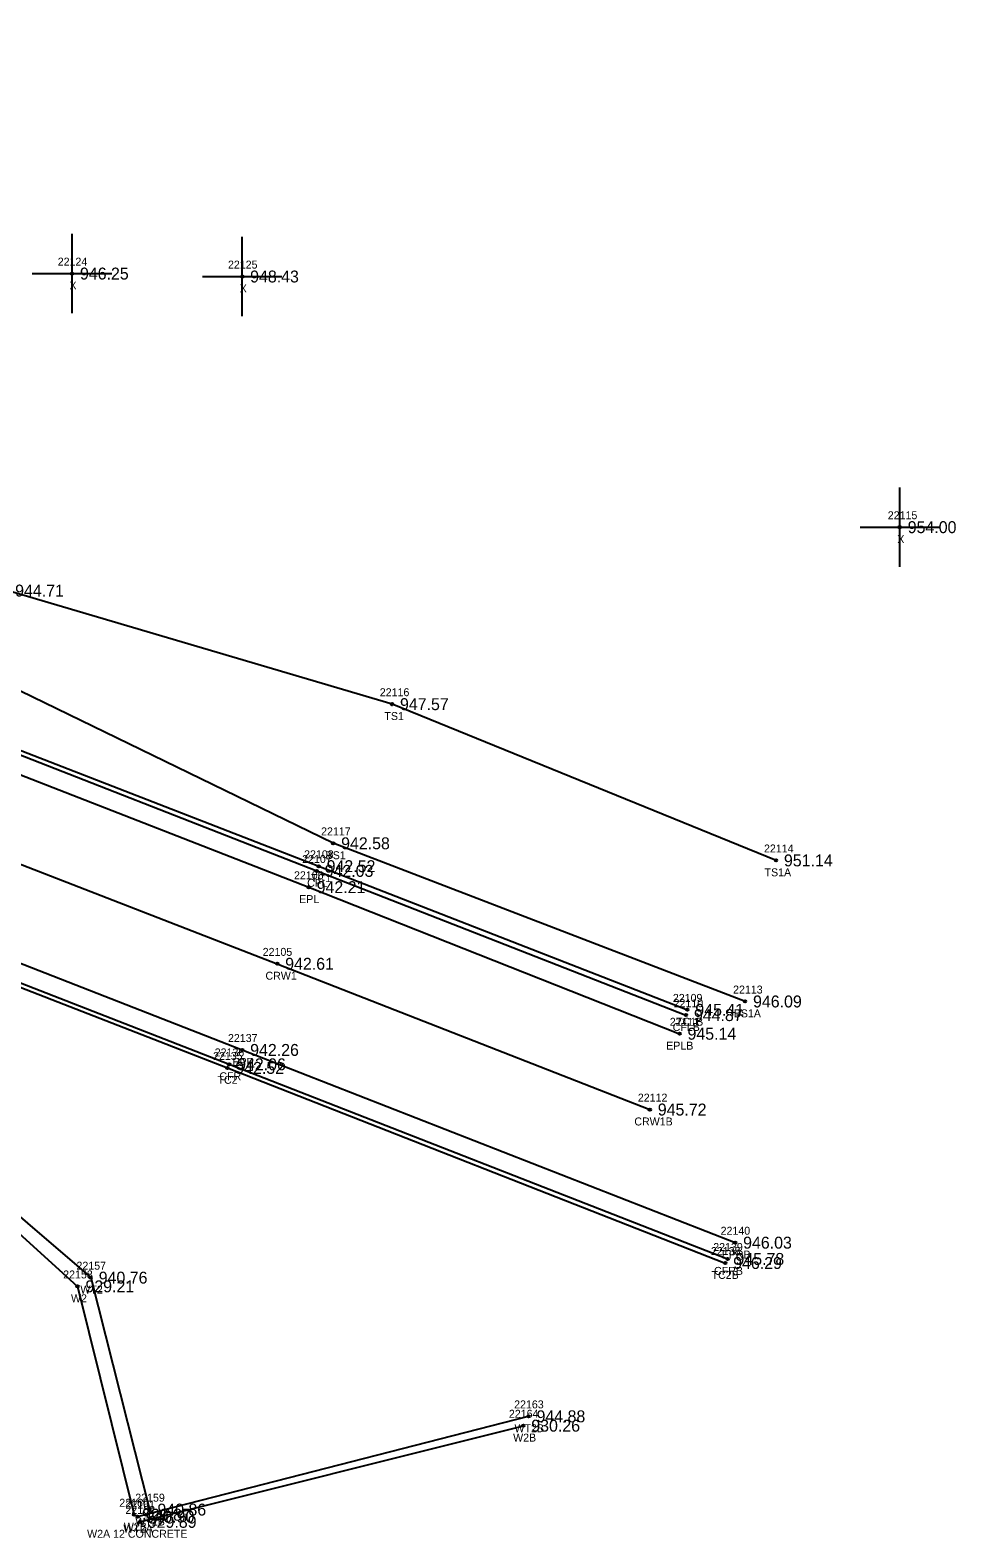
# Model space of a CAD drawing. Extents: x 1576181 to 1577685, y 1099396 to 1101490.
# Drawn here: x 1577568.7 to 1577685.3, y 1100751.9 to 1100941.6 of the extents above; entities that cross this region are included whole.
import ezdxf

# ---------------------------------------------------------------- set-up
doc = ezdxf.new("R2010")
doc.units = 0
for name, color, linetype in [('RD_DTM_BkLn1', 7, 'Continuous'), ('RD_DTM_BkLn2', 7, 'Continuous'), ('RD_DTM_BkLn_txCode', 7, 'Continuous'), ('RD_EX_BldgApp', 7, 'Continuous'), ('RD_EX_Conc', 7, 'Continuous'), ('RD_EX_Conc_txCode', 7, 'Continuous'), ('RD_EX_Misc', 7, 'Continuous'), ('RD_EX_Misc_txCode', 7, 'Continuous'), ('RD_EX_Road', 7, 'Continuous'), ('RD_EX_Road_txCode', 7, 'Continuous'), ('RD_EX_TX_Conc_ELEV', 7, 'Continuous'), ('RD_EX_TX_Misc_ELEV', 7, 'Continuous'), ('RD_EX_TX_Road_ELEV', 7, 'Continuous'), ('RD_HC_Survey_ELEV', 7, 'Continuous'), ('RD_HC_Survey_txCode', 7, 'Continuous'), ('RD_SMD_Locator', 7, 'Continuous')]:
    doc.layers.add(name, color=color, linetype=linetype)

msp = doc.modelspace()

# ---------------------------------------------------------------- linework, layer by layer
at = {"layer": 'RD_DTM_BkLn1'}
msp.add_lwpolyline([(1577238.59, 1101054.64), (1577263.64, 1101036.24), (1577303.95, 1101006.72), (1577344.58, 1100977.95), (1577386.9, 1100948.15), (1577426.17, 1100919.26), (1577465.69, 1100889.09), (1577507.94, 1100862.82), (1577553.41, 1100842.12), (1577599.84, 1100824.14), (1577646.74, 1100805.8)], dxfattribs=at)
at = {"layer": 'RD_DTM_BkLn2'}
msp.add_line((1577582.27, 1100754.58), (1577631.48, 1100767.2), dxfattribs=at)
for points in [[(1577662.62, 1100837.15), (1577614.29, 1100856.81), (1577565.85, 1100871.1), (1577528.46, 1100887.57), (1577543.38, 1100922.33)], [(1577395.54, 1100920.23), (1577401.33, 1100918.75), (1577405.58, 1100916.45), (1577417.84, 1100907.66), (1577459.24, 1100877.93), (1577501.01, 1100850.46), (1577548.36, 1100828.61), (1577593.56, 1100811.04), (1577656.23, 1100786.49)], [(1577522.49, 1100891.97), (1577519.6, 1100884.45), (1577518.53, 1100878.68), (1577519.8, 1100874.02), (1577525.54, 1100868.86), (1577559.77, 1100854.01), (1577605.06, 1100836.42), (1577651.47, 1100818.35)], [(1577658.73, 1100819.4), (1577606.88, 1100839.3), (1577561.44, 1100861.37), (1577525.46, 1100877.1), (1577521.55, 1100887.46)], [(1577432.53, 1100853.96), (1577434.36, 1100852.19), (1577447.88, 1100856.09), (1577457.13, 1100856.82), (1577470.14, 1100851.87), (1577480.17, 1100839.59), (1577486.13, 1100817.13), (1577494.64, 1100804.62), (1577509.91, 1100799.91), (1577531.35, 1100805.03), (1577541.32, 1100806.67), (1577560.38, 1100798.33), (1577576.37, 1100784.65), (1577583.76, 1100755.46)]]:
    msp.add_lwpolyline(points, dxfattribs=at)
at = {"layer": 'RD_EX_BldgApp'}
msp.add_line((1577582.55, 1100753.92), (1577630.82, 1100766.02), dxfattribs=at)
msp.add_lwpolyline([(1577431.47, 1100853.57), (1577434.21, 1100851.02), (1577448.25, 1100855.22), (1577457, 1100855.58), (1577470.32, 1100850.24), (1577479.05, 1100838.66), (1577484.72, 1100816.57), (1577493.67, 1100803.21), (1577510, 1100798.11), (1577531.96, 1100803.27), (1577542, 1100804.92), (1577559.8, 1100797.02), (1577574.7, 1100783.55), (1577581.82, 1100754.82)], dxfattribs=at)
at = {"layer": 'RD_EX_Conc'}
for points in [[(1577395.74, 1100920.66), (1577401.57, 1100919.25), (1577405.99, 1100917), (1577418.29, 1100908.16), (1577459.56, 1100878.43), (1577501.42, 1100850.96), (1577548.66, 1100829.07), (1577593.79, 1100811.49), (1577656.52, 1100787)], [(1577521.96, 1100892.21), (1577519.03, 1100884.74), (1577517.86, 1100878.7), (1577519.28, 1100873.69), (1577525.34, 1100868.31), (1577559.49, 1100853.53), (1577604.81, 1100835.83), (1577651.29, 1100817.68)]]:
    msp.add_lwpolyline(points, dxfattribs=at)
at = {"layer": 'RD_EX_Misc'}
for p, q in [((1577574.01, 1100905.99), (1577574.01, 1100915.99)), ((1577595.43, 1100905.62), (1577595.43, 1100915.62)), ((1577569.01, 1100910.99), (1577579.01, 1100910.99)), ((1577590.43, 1100910.62), (1577600.43, 1100910.62)), ((1577678.2, 1100874.08), (1577678.2, 1100884.08)), ((1577673.2, 1100879.08), (1577683.2, 1100879.08))]:
    msp.add_line(p, q, dxfattribs=at)
at = {"layer": 'RD_EX_Road'}
for points in [[(1577532.83, 1100925.69), (1577520.07, 1100893.35), (1577517.12, 1100885.44), (1577515.83, 1100878.7), (1577517.19, 1100872.6), (1577524.62, 1100866.38), (1577558.24, 1100851.54), (1577603.8, 1100833.78), (1577650.48, 1100815.34)], [(1577419.5, 1100910.06), (1577460.72, 1100880.37), (1577502.61, 1100852.88), (1577549.63, 1100831.2), (1577595.43, 1100813.3), (1577657.48, 1100789.05)]]:
    msp.add_lwpolyline(points, dxfattribs=at)
at = {"layer": 'RD_SMD_Locator'}
for centre in [(1577574.01, 1100910.99), (1577595.43, 1100910.62), (1577678.2, 1100879.08), (1577614.29, 1100856.81), (1577606.88, 1100839.3), (1577605.06, 1100836.42), (1577662.62, 1100837.15), (1577604.81, 1100835.83), (1577603.8, 1100833.78), (1577599.84, 1100824.14), (1577658.73, 1100819.4), (1577651.29, 1100817.68), (1577651.47, 1100818.35), (1577650.48, 1100815.34), (1577595.43, 1100813.3), (1577593.79, 1100811.49), (1577593.56, 1100811.04), (1577646.74, 1100805.8), (1577657.48, 1100789.05), (1577656.52, 1100787), (1577656.23, 1100786.49), (1577574.7, 1100783.55), (1577576.37, 1100784.65), (1577630.82, 1100766.02), (1577631.48, 1100767.2), (1577581.82, 1100754.82), (1577582.27, 1100754.58), (1577583.76, 1100755.46), (1577582.55, 1100753.92)]:
    msp.add_circle(centre, 0.15, dxfattribs=at)

# ---------------------------------------------------------------- texts
at = {"layer": 'RD_DTM_BkLn_txCode'}
for s, p in [('22116', (1577612.75, 1100857.81)), ('TS1', (1577613.33, 1100854.81)), ('22117', (1577605.36, 1100840.3)), ('BS1', (1577605.93, 1100837.3)), ('22114', (1577661.11, 1100838.15)), ('TS1A', (1577661.18, 1100835.15)), ('22113', (1577657.22, 1100820.4)), ('BS1A', (1577657.3, 1100817.4))]:
    msp.add_text(s, height=1, dxfattribs=at).set_placement(p)
at = {"layer": 'RD_EX_Conc_txCode'}
for s, p in [('22108', (1577603.22, 1100837.42)), ('22107', (1577602.98, 1100836.83)), ('CFL', (1577603.61, 1100833.83)), ('TC1', (1577604.09, 1100834.42)), ('22109', (1577649.64, 1100819.35)), ('22110', (1577649.74, 1100818.68)), ('TC1B', (1577650.04, 1100816.35)), ('CFLB', (1577649.61, 1100815.68)), ('22136', (1577591.97, 1100812.49)), ('22135', (1577591.76, 1100812.04)), ('TC2', (1577592.32, 1100809.04)), ('CFR', (1577592.56, 1100809.49)), ('22139', (1577654.72, 1100788)), ('22138', (1577654.43, 1100787.49)), ('TC2B', (1577654.51, 1100784.49)), ('CFRB', (1577654.82, 1100785))]:
    msp.add_text(s, height=1, dxfattribs=at).set_placement(p)
at = {"layer": 'RD_EX_Misc_txCode'}
for s, p in [('22124', (1577572.21, 1100911.99)), ('22125', (1577593.64, 1100911.62)), ('X', (1577573.69, 1100908.99)), ('X', (1577595.12, 1100908.62)), ('22115', (1577676.69, 1100880.08)), ('X', (1577677.89, 1100877.08)), ('22158', (1577572.9, 1100784.55)), ('22157', (1577574.57, 1100785.65)), ('WT2', (1577575.06, 1100782.65)), ('W2', (1577573.88, 1100781.55)), ('22164', (1577629, 1100767.02)), ('22163', (1577629.66, 1100768.2)), ('WT2B', (1577629.7, 1100765.2)), ('W2B', (1577629.53, 1100764.02)), ('22160', (1577579.96, 1100755.82)), ('22161', (1577580.73, 1100755.58)), ('22159', (1577581.97, 1100756.46)), ('22162', (1577580.73, 1100754.92)), ('W2A 12 CONCRETE', (1577575.91, 1100751.92)), ('WT2A', (1577580.47, 1100752.58)), ('W2B', (1577580.53, 1100752.82)), ('WT2B', (1577581.98, 1100753.46))]:
    msp.add_text(s, height=1, dxfattribs=at).set_placement(p)
at = {"layer": 'RD_EX_Road_txCode'}
for s, p in [('22106', (1577601.95, 1100834.78)), ('EPL', (1577602.6, 1100831.78)), ('22111', (1577649.25, 1100816.34)), ('22137', (1577593.64, 1100814.3)), ('EPLB', (1577648.8, 1100813.34)), ('EPR', (1577594.2, 1100811.3)), ('22140', (1577655.65, 1100790.05)), ('EPRB', (1577655.78, 1100787.05))]:
    msp.add_text(s, height=1, dxfattribs=at).set_placement(p)
at = {"layer": 'RD_EX_TX_Conc_ELEV'}
for s, p in [('942.03', (1577605.81, 1100835.08)), ('942.52', (1577606.06, 1100835.67)), ('945.41', (1577652.47, 1100817.6)), ('944.87', (1577652.29, 1100816.93)), ('942.52', (1577594.56, 1100810.29)), ('942.06', (1577594.79, 1100810.74)), ('946.29', (1577657.23, 1100785.74)), ('945.78', (1577657.52, 1100786.25))]:
    msp.add_text(s, height=1.5, dxfattribs=at).set_placement(p)
at = {"layer": 'RD_EX_TX_Misc_ELEV'}
for s, p in [('946.25', (1577575.01, 1100910.24)), ('948.43', (1577596.43, 1100909.87)), ('954.00', (1577679.2, 1100878.33)), ('944.71', (1577566.85, 1100870.35)), ('947.57', (1577615.29, 1100856.06)), ('942.58', (1577607.88, 1100838.55)), ('951.14', (1577663.62, 1100836.4)), ('946.09', (1577659.73, 1100818.65)), ('940.76', (1577577.37, 1100783.9)), ('929.21', (1577575.7, 1100782.8)), ('944.88', (1577632.48, 1100766.45)), ('930.26', (1577631.82, 1100765.27)), ('929.87', (1577582.82, 1100754.07)), ('940.90', (1577583.27, 1100753.83)), ('929.89', (1577583.55, 1100753.17)), ('940.86', (1577584.76, 1100754.71))]:
    msp.add_text(s, height=1.5, dxfattribs=at).set_placement(p)
at = {"layer": 'RD_EX_TX_Road_ELEV'}
for s, p in [('942.21', (1577604.8, 1100833.03)), ('945.14', (1577651.48, 1100814.59)), ('942.26', (1577596.43, 1100812.55)), ('946.03', (1577658.48, 1100788.3))]:
    msp.add_text(s, height=1.5, dxfattribs=at).set_placement(p)
at = {"layer": 'RD_HC_Survey_ELEV'}
for s, p in [('942.61', (1577600.84, 1100823.39)), ('945.72', (1577647.74, 1100805.05))]:
    msp.add_text(s, height=1.5, dxfattribs=at).set_placement(p)
at = {"layer": 'RD_HC_Survey_txCode'}
for s, p in [('22105', (1577598.01, 1100825.14)), ('CRW1', (1577598.36, 1100822.14)), ('22112', (1577645.23, 1100806.8)), ('CRW1B', (1577644.79, 1100803.8))]:
    msp.add_text(s, height=1, dxfattribs=at).set_placement(p)

doc.saveas('drawing.dxf')
